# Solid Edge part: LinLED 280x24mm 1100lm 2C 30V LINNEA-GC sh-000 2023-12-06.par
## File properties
Author: jaroslaw.przewlocki
Template: iso metric part.par
Last saved by: jaroslaw.przewlocki
Revision: 3
Application: Solid Edge
Gęstość: 0,000 kg/m^3
Dokładność: 0,990
Username: jaroslaw.przewlocki
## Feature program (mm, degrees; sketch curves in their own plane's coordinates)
body "unnamed Body 1"
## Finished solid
Body 1: solid body, 2294 faces, 5880 edges, 3823 vertices, 3 separate solids.
  Faces by surface: plane 1696, cylinder 252, cone 150, spline 113, swept 47, sphere 18, torus 10, spun 8
  Edges by curve: line 4648, circle 660, curve on surface 352, spline 142, ellipse 66, intersection 12
Bounding box of the edges (mm; curved faces can reach further): 280.000 x 5.100 x 24.000, from (-140, -3.5, -12) to (140, 1.6, 12).
Cylindrical faces by radius (mm): R0.2 x46, R0.2169 x6, R0.25 x12, R0.3 x90, R0.3373 x6, R0.4 x8, R0.4006 x2, R0.4008 x2, R0.525 x2, R0.6 x50, R1 x8, R1.1 x4, R1.2 x10, R2.1 x6
Conical faces (half-angle, radius in mm at the cone's reference point): 0.5 deg R0.5056 x4, 0.5 deg R1.0082 x4, 1 deg R0.5511 x2, 3.5 deg R0.2 x120, 10 deg R0.2132 x4, 10 deg R0.4132 x4, 18.8604 deg R1.0669 x4, 27.363 deg R0.6214 x2, 45 deg R0.575 x2, 45 deg R0.625 x4
Toroidal faces (ring radius, tube radius in mm): R0.8 r0.2 x4, R0.8522 r0.3 x2, R0.9002 r0.2 x2, R0.9018 r0.2 x2
Spherical faces by radius (mm): R0.2 x12, R0.2761 x2, R0.6 x4
Planar faces by outward normal: +x 145, +y 133, +z 243, -x 140, -y 376, -z 249, oblique 410
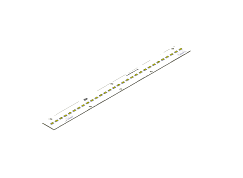
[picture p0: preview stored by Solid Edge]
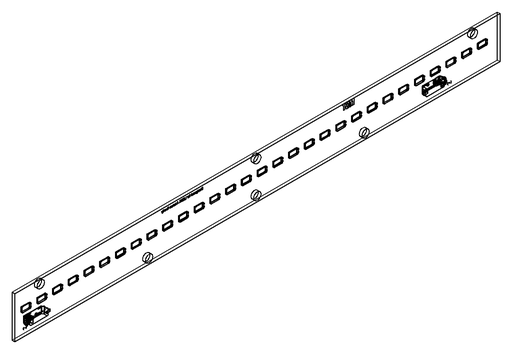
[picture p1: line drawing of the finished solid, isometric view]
